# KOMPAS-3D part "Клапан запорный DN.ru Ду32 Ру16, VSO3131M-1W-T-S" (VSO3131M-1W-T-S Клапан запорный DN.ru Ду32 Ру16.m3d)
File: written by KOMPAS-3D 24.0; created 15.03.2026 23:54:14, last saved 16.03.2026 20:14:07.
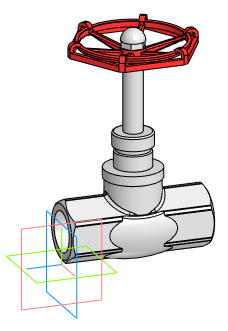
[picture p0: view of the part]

Document properties: Автор: artiomk228874@gmail.com; Полное имя файла: VSO3131M-1W-T-S Клапан запорный DN.ru Ду32 Ру16.cdw

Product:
- Body: Тело 1  | qty 1
    Масса: 0.617629
- Part/product: Клапан запорный DN.ru Ду32 Ру16  | designation VSO3131M-1W-T-S
    Масса: 0.76
    Раздел спецификации: Прочие изделия
    Форматы листов документа: A2
    Примечание: D100-03672
    additional columns: 94d3474e-3e6e-4ddd-ad0b-ef51eb5e31da; VSO3131M-1W-T-S; Сталь 10 ГОСТ 1050-2013; artiomk228874@gmail.com; c; Шероховатость не задана; Да

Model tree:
1. Операция без истории:1

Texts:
  VSO3131M-1W-T-S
